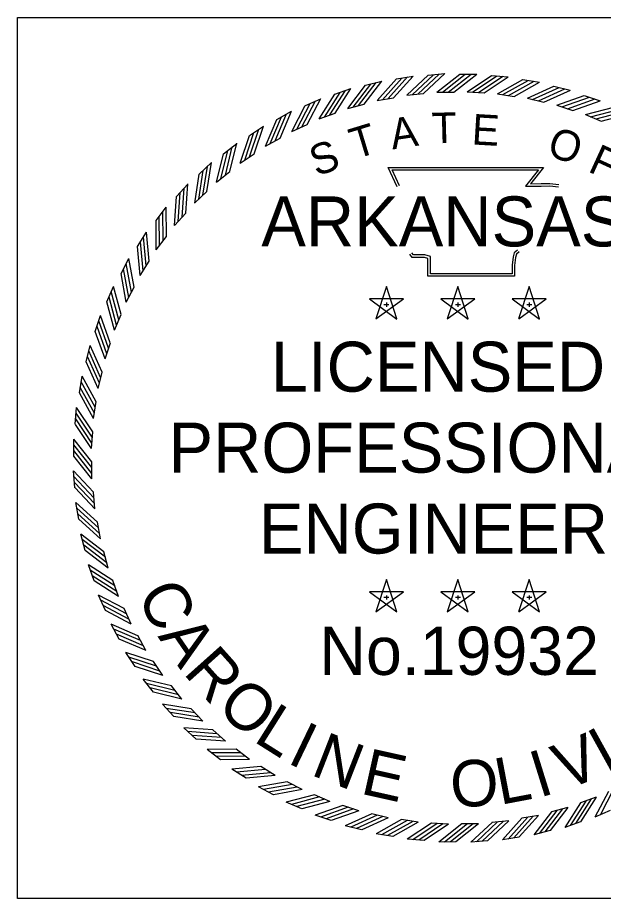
# Model space of a CAD drawing. Extents: x 0 to 1228740, y 0 to 152440.
# Drawn here: x 30.667 to 32.49, y 23.111 to 25.853 of the extents above; entities that cross this region are included whole.
import ezdxf

# ---------------------------------------------------------------- set-up
doc = ezdxf.new("R2010")
doc.units = 0
doc.layers.add('R_No Plot', color=7, linetype='Continuous')
doc.layers.add('STAMP', color=7, linetype='Continuous')

msp = doc.modelspace()

# ---------------------------------------------------------------- linework, layer by layer
at = {"layer": 'R_No Plot'}
msp.add_lwpolyline([(30.6665, 25.8526), (33.4082, 25.8526), (33.4082, 23.1109), (30.6665, 23.1109)], close=True, dxfattribs=at)
at = {"layer": 'STAMP'}
for p, q in [((31.846, 25.6616), (31.8976, 25.6707)), ((31.9441, 25.6733), (31.9963, 25.6782)), ((32.0433, 25.6763), (32.0957, 25.6763)), ((32.1415, 25.6723), (32.1937, 25.6685)), ((31.7492, 25.6419), (31.7999, 25.6552)), ((32.2394, 25.6596), (32.2912, 25.6515)), ((32.336, 25.6389), (32.3869, 25.6265)), ((31.6544, 25.6142), (31.7038, 25.6316)), ((31.878, 25.6113), (31.9303, 25.6161)), ((31.9718, 25.6205), (32.0243, 25.6205)), ((32.0661, 25.622), (32.1184, 25.6181)), ((32.1601, 25.6157), (32.212, 25.6075)), ((32.4305, 25.6102), (32.4802, 25.5936)), ((31.5622, 25.5787), (31.61, 25.6002)), ((31.6942, 25.5697), (31.745, 25.5831)), ((31.7853, 25.5943), (31.837, 25.6034)), ((32.2533, 25.6016), (32.3044, 25.5892)), ((31.4732, 25.5358), (31.5191, 25.5611)), ((31.6056, 25.5377), (31.6551, 25.5552)), ((32.3451, 25.5799), (32.3949, 25.5633)), ((32.4347, 25.5507), (32.483, 25.53)), ((31.3881, 25.4857), (31.4317, 25.5147)), ((31.5198, 25.4985), (31.5677, 25.5201)), ((31.4376, 25.4524), (31.4836, 25.4778)), ((31.3074, 25.4287), (31.3485, 25.4612)), ((31.3595, 25.3996), (31.4032, 25.4287)), ((31.2317, 25.3652), (31.2699, 25.4011)), ((31.2861, 25.3405), (31.3272, 25.3732)), ((31.1615, 25.2957), (31.1967, 25.3346)), ((31.2177, 25.2756), (31.256, 25.3115)), ((31.0973, 25.2207), (31.1291, 25.2623)), ((31.1549, 25.2053), (31.1902, 25.2442)), ((31.0395, 25.1406), (31.0677, 25.1847)), ((31.0982, 25.13), (31.1301, 25.1717)), ((30.9885, 25.056), (31.013, 25.1023)), ((31.0479, 25.0503), (31.0762, 25.0945)), ((30.9447, 24.9674), (30.9653, 25.0156)), ((31.0043, 24.9667), (31.0289, 25.0131)), ((31.8143, 25.0151), (31.7815, 24.9145)), ((31.847, 24.9146), (31.8144, 25.0152)), ((32.0366, 25.0151), (32.0038, 24.9145)), ((32.0693, 24.9146), (32.0367, 25.0152)), ((32.2589, 25.0151), (32.2261, 24.9145)), ((32.2915, 24.9146), (32.2589, 25.0152)), ((31.8672, 24.9767), (31.7614, 24.9768)), ((31.7615, 24.9767), (31.847, 24.9144)), ((31.7817, 24.9146), (31.8673, 24.9767)), ((31.8068, 24.9598), (31.8225, 24.9598)), ((31.8144, 24.9654), (31.8144, 24.9522)), ((32.0894, 24.9767), (31.9837, 24.9768)), ((31.9837, 24.9767), (32.0693, 24.9144)), ((32.0039, 24.9146), (32.0896, 24.9767)), ((32.0291, 24.9598), (32.0448, 24.9598)), ((32.0367, 24.9654), (32.0367, 24.9522)), ((32.3117, 24.9767), (32.2059, 24.9768)), ((32.206, 24.9767), (32.2915, 24.9144)), ((32.2262, 24.9146), (32.3118, 24.9767)), ((32.2513, 24.9598), (32.2671, 24.9598)), ((32.259, 24.9654), (32.259, 24.9522)), ((30.9083, 24.8756), (30.9248, 24.9253)), ((30.9678, 24.8798), (30.9885, 24.9281)), ((30.9386, 24.7901), (30.9552, 24.84)), ((30.8796, 24.7811), (30.892, 24.832)), ((30.8588, 24.6845), (30.867, 24.7363)), ((30.9169, 24.6984), (30.9293, 24.7494)), ((30.9028, 24.6052), (30.911, 24.6571)), ((30.8461, 24.5866), (30.85, 24.6388)), ((30.8415, 24.4879), (30.8411, 24.5403)), ((30.8965, 24.5111), (30.9003, 24.5635)), ((30.898, 24.4169), (30.8975, 24.4694)), ((30.8451, 24.3892), (30.8403, 24.4413)), ((30.9072, 24.3231), (30.9024, 24.3754)), ((30.8568, 24.2911), (30.8477, 24.3427)), ((30.9242, 24.2303), (30.915, 24.2821)), ((30.8766, 24.1943), (30.8633, 24.245)), ((30.9487, 24.1393), (30.9354, 24.1901)), ((30.9043, 24.0995), (30.8868, 24.1489)), ((30.9807, 24.0507), (30.9632, 24.1002)), ((31.8143, 24.1037), (31.7815, 24.0031)), ((31.847, 24.0032), (31.8144, 24.1038)), ((32.0366, 24.1037), (32.0038, 24.0031)), ((32.0693, 24.0032), (32.0367, 24.1038)), ((32.2589, 24.1037), (32.2261, 24.0031)), ((32.2915, 24.0032), (32.2589, 24.1038)), ((30.9398, 24.0073), (30.9183, 24.0551)), ((31.8672, 24.0653), (31.7614, 24.0654)), ((31.7615, 24.0653), (31.847, 24.0031)), ((31.7817, 24.0032), (31.8673, 24.0653)), ((31.8068, 24.0484), (31.8225, 24.0484)), ((31.8144, 24.0541), (31.8144, 24.0408)), ((32.0894, 24.0653), (31.9837, 24.0654)), ((31.9837, 24.0653), (32.0693, 24.0031)), ((32.0039, 24.0032), (32.0896, 24.0653)), ((32.0291, 24.0484), (32.0448, 24.0484)), ((32.0367, 24.0541), (32.0367, 24.0408)), ((32.3117, 24.0653), (32.2059, 24.0654)), ((32.206, 24.0653), (32.2915, 24.0031)), ((32.2262, 24.0032), (32.3118, 24.0653)), ((32.2513, 24.0484), (32.2671, 24.0484)), ((32.259, 24.0541), (32.259, 24.0408)), ((31.0199, 23.9649), (30.9984, 24.0128)), ((30.9827, 23.9183), (30.9573, 23.9642)), ((31.0661, 23.8827), (31.0407, 23.9287)), ((31.0328, 23.8332), (31.0038, 23.8768)), ((31.1189, 23.8046), (31.0897, 23.8483)), ((31.0898, 23.7525), (31.0572, 23.7936)), ((31.1779, 23.7311), (31.1453, 23.7723)), ((31.1533, 23.6768), (31.1174, 23.715)), ((31.2429, 23.6628), (31.2069, 23.7011)), ((31.2227, 23.6066), (31.1839, 23.6417)), ((31.3132, 23.6), (31.2742, 23.6352)), ((31.2978, 23.5424), (31.2562, 23.5742)), ((31.3885, 23.5433), (31.3467, 23.5752)), ((31.3779, 23.4846), (31.3338, 23.5128)), ((31.4682, 23.493), (31.424, 23.5213)), ((31.5518, 23.4494), (31.5054, 23.474)), ((31.4625, 23.4336), (31.4162, 23.4581)), ((31.6387, 23.4129), (31.5904, 23.4335)), ((32.4678, 23.4258), (32.4183, 23.4083)), ((31.551, 23.3897), (31.5028, 23.4103)), ((31.7283, 23.3837), (31.6785, 23.4003)), ((32.3791, 23.3938), (32.3283, 23.3805)), ((31.6429, 23.3534), (31.5931, 23.3699)), ((31.8201, 23.362), (31.769, 23.3744)), ((32.2881, 23.3693), (32.2364, 23.3601)), ((32.5112, 23.3848), (32.4634, 23.3634)), ((31.7374, 23.3247), (31.6865, 23.3371)), ((31.9133, 23.3479), (31.8614, 23.3561)), ((32.0073, 23.3416), (31.9549, 23.3454)), ((32.1016, 23.343), (32.0491, 23.3426)), ((32.1954, 23.3523), (32.1431, 23.3475)), ((32.419, 23.3494), (32.3696, 23.3319)), ((31.834, 23.3039), (31.7822, 23.3121)), ((32.3242, 23.3217), (32.2735, 23.3084)), ((31.9319, 23.2912), (31.8797, 23.2951)), ((32.0306, 23.2866), (31.9782, 23.2861)), ((32.1293, 23.2902), (32.0771, 23.2854)), ((32.2274, 23.3019), (32.1758, 23.2928))]:
    msp.add_line(p, q, dxfattribs=at)
for points in [[(31.8018, 25.597), (31.8626, 25.6643)], [(31.8197, 25.6006), (31.8804, 25.6679)], [(31.8369, 25.6034), (31.8976, 25.6708)], [(31.8779, 25.6112), (31.944, 25.6733)], [(31.8947, 25.6126), (31.9608, 25.6747)], [(31.9128, 25.6147), (31.9789, 25.6768)], [(31.9302, 25.6161), (31.9963, 25.6782)], [(31.9717, 25.6205), (32.0432, 25.6762)], [(31.9886, 25.6203), (32.0601, 25.6761)], [(32.0068, 25.6207), (32.0783, 25.6765)], [(32.0243, 25.6205), (32.0958, 25.6763)], [(32.066, 25.6219), (32.1414, 25.6723)], [(32.0828, 25.6205), (32.1582, 25.6709)], [(32.101, 25.6196), (32.1764, 25.67)], [(32.1184, 25.6182), (32.1938, 25.6685)], [(31.6942, 25.5697), (31.7491, 25.6418)], [(31.7105, 25.5738), (31.7655, 25.6459)], [(31.728, 25.5788), (31.783, 25.6509)], [(31.745, 25.5831), (31.7999, 25.6552)], [(31.7852, 25.5942), (31.8459, 25.6616)], [(32.16, 25.6156), (32.2393, 25.6596)], [(32.1767, 25.6128), (32.256, 25.6568)], [(32.1947, 25.6104), (32.274, 25.6544)], [(32.2119, 25.6075), (32.2912, 25.6515)], [(32.2532, 25.6016), (32.3359, 25.6388)], [(31.6055, 25.5377), (31.6543, 25.6141)], [(31.6215, 25.5431), (31.6703, 25.6196)], [(31.6385, 25.5496), (31.6873, 25.626)], [(31.655, 25.5553), (31.7038, 25.6317)], [(32.2696, 25.5974), (32.3523, 25.6347)], [(32.2874, 25.5935), (32.37, 25.6308)], [(32.3043, 25.5892), (32.387, 25.6265)], [(32.345, 25.5799), (32.4304, 25.6102)], [(31.5352, 25.5052), (31.5776, 25.5854)], [(31.5517, 25.5131), (31.594, 25.5932)], [(31.5677, 25.5201), (31.61, 25.6003)], [(32.3609, 25.5744), (32.4464, 25.6047)], [(32.3783, 25.569), (32.4638, 25.5993)], [(32.3948, 25.5633), (32.4803, 25.5937)], [(31.4682, 25.4695), (31.5038, 25.5529)], [(31.4835, 25.4778), (31.5191, 25.5612)], [(31.5198, 25.4985), (31.5621, 25.5786)], [(32.4346, 25.5506), (32.5223, 25.5738)], [(32.4501, 25.5439), (32.5377, 25.567)], [(32.4669, 25.5371), (32.5546, 25.5602)], [(32.4829, 25.5301), (32.5706, 25.5532)], [(31.4376, 25.4523), (31.4732, 25.5357)], [(31.4524, 25.4603), (31.488, 25.5437)], [(31.3886, 25.4192), (31.4171, 25.5052)], [(31.4032, 25.4287), (31.4317, 25.5148)], [(31.3595, 25.3995), (31.3881, 25.4856)], [(31.3736, 25.4087), (31.4022, 25.4948)], [(31.3134, 25.3624), (31.3347, 25.4506)], [(31.3271, 25.3732), (31.3485, 25.4613)], [(31.286, 25.3405), (31.3074, 25.4286)], [(31.2993, 25.3508), (31.3207, 25.4389)], [(31.2431, 25.2997), (31.2571, 25.3893)], [(31.2559, 25.3115), (31.27, 25.4011)], [(31.2177, 25.2755), (31.2317, 25.3651)], [(31.2301, 25.287), (31.2441, 25.3765)], [(31.8481, 25.3255), (31.8201, 25.386), (32.3034, 25.3863), (32.2631, 25.3356), (32.2959, 25.336), (32.3233, 25.3364), (32.3507, 25.3334)], [(31.855, 25.3288), (31.8321, 25.3784), (32.2876, 25.3787), (32.247, 25.3277), (32.296, 25.3284), (32.3229, 25.3287), (32.3499, 25.3258)], [(31.1901, 25.2442), (31.1967, 25.3347)], [(31.1664, 25.2176), (31.1729, 25.308)], [(31.1783, 25.2314), (31.1848, 25.3218)], [(31.1549, 25.2052), (31.1615, 25.2956)], [(31.13, 25.1717), (31.1291, 25.2624)], [(31.1086, 25.1432), (31.1076, 25.2339)], [(31.1193, 25.1579), (31.1184, 25.2486)], [(31.0982, 25.1299), (31.0973, 25.2206)], [(31.0666, 25.0799), (31.0582, 25.1701)], [(31.0761, 25.0945), (31.0677, 25.1848)], [(31.0571, 25.0643), (31.0487, 25.1546)], [(31.0479, 25.0502), (31.0395, 25.1405)], [(32.2273, 25.123), (32.219, 25.1163), (32.2163, 25.1063), (32.2136, 25.0812), (32.2136, 25.0478), (31.9438, 25.0478), (31.9438, 25.0929), (31.9438, 25.1029), (31.9328, 25.1063), (31.8944, 25.1063), (31.8876, 25.1167)], [(32.2224, 25.129), (32.2123, 25.1207), (32.2088, 25.1077), (32.2059, 25.0816), (32.2059, 25.0555), (31.9514, 25.0555), (31.9514, 25.0929), (31.9514, 25.1086), (31.934, 25.1139), (31.8986, 25.1139), (31.894, 25.1209)], [(31.0205, 24.9977), (31.0047, 25.087)], [(31.0288, 25.0131), (31.013, 25.1023)], [(31.0124, 24.9814), (30.9965, 25.0707)], [(31.0043, 24.9666), (30.9885, 25.0559)], [(30.9884, 24.928), (30.9652, 25.0157)], [(30.9746, 24.8951), (30.9514, 24.9828)], [(30.9814, 24.912), (30.9582, 24.9997)], [(30.9678, 24.8797), (30.9447, 24.9674)], [(30.9551, 24.8399), (30.9248, 24.9254)], [(30.9495, 24.8234), (30.9191, 24.9089)], [(30.9386, 24.7901), (30.9083, 24.8755)], [(30.9441, 24.806), (30.9138, 24.8915)], [(30.925, 24.7325), (30.8877, 24.8151)], [(30.9292, 24.7494), (30.892, 24.8321)], [(30.921, 24.7147), (30.8838, 24.7973)], [(30.9169, 24.6983), (30.8796, 24.781)], [(30.9109, 24.657), (30.867, 24.7363)], [(30.9081, 24.6398), (30.8641, 24.7191)], [(30.9028, 24.6051), (30.8589, 24.6844)], [(30.9056, 24.6218), (30.8617, 24.7011)], [(30.8989, 24.5461), (30.8485, 24.6215)], [(30.9003, 24.5635), (30.8499, 24.6389)], [(30.8979, 24.5279), (30.8476, 24.6033)], [(30.8965, 24.5111), (30.8462, 24.5865)], [(30.8974, 24.4693), (30.841, 24.5403)], [(30.8974, 24.4519), (30.841, 24.5229)], [(30.898, 24.4337), (30.8416, 24.5047)], [(30.898, 24.4168), (30.8416, 24.4878)], [(30.9024, 24.3753), (30.8403, 24.4414)], [(30.9038, 24.3579), (30.8417, 24.424)], [(30.9059, 24.3398), (30.8438, 24.4059)], [(30.9073, 24.323), (30.8452, 24.3891)], [(30.915, 24.282), (30.8477, 24.3427)], [(30.9179, 24.2648), (30.8506, 24.3255)], [(30.9215, 24.2469), (30.8541, 24.3076)], [(30.9242, 24.2303), (30.8569, 24.291)], [(30.9354, 24.1901), (30.8632, 24.245)], [(30.9396, 24.1731), (30.8675, 24.2281)], [(30.9447, 24.1556), (30.8725, 24.2106)], [(30.9488, 24.1393), (30.8767, 24.1942)], [(30.9632, 24.1001), (30.8868, 24.1489)], [(30.9689, 24.0836), (30.8925, 24.1324)], [(30.9753, 24.0666), (30.8989, 24.1154)], [(30.9808, 24.0506), (30.9044, 24.0994)], [(30.9984, 24.0128), (30.9182, 24.0551)], [(31.0054, 23.9968), (30.9252, 24.0391)], [(31.0132, 23.9803), (30.9331, 24.0227)], [(31.02, 23.9649), (30.9398, 24.0072)], [(31.0407, 23.9286), (30.9573, 23.9642)], [(31.049, 23.9133), (30.9656, 23.9488)], [(31.0581, 23.8975), (30.9747, 23.9331)], [(31.0662, 23.8827), (30.9828, 23.9183)], [(31.0897, 23.8483), (31.0037, 23.8768)], [(31.0993, 23.8336), (31.0132, 23.8622)], [(31.1097, 23.8187), (31.0237, 23.8473)], [(31.119, 23.8046), (31.0329, 23.8332)], [(31.1453, 23.7722), (31.0572, 23.7936)], [(31.156, 23.7584), (31.0679, 23.7798)], [(31.1676, 23.7444), (31.0795, 23.7658)], [(31.178, 23.7311), (31.0899, 23.7525)], [(31.2069, 23.701), (31.1174, 23.715)], [(31.2188, 23.6882), (31.1292, 23.7022)], [(31.2315, 23.6752), (31.1419, 23.6892)], [(31.2429, 23.6628), (31.1533, 23.6768)], [(31.2742, 23.6352), (31.1838, 23.6417)], [(31.2871, 23.6234), (31.1967, 23.6299)], [(31.3009, 23.6115), (31.2104, 23.618)], [(31.3133, 23.6), (31.2228, 23.6066)], [(31.3468, 23.5751), (31.2561, 23.5742)], [(31.3605, 23.5644), (31.2699, 23.5635)], [(31.3752, 23.5537), (31.2846, 23.5527)], [(31.3886, 23.5433), (31.2979, 23.5424)], [(31.424, 23.5212), (31.3337, 23.5128)], [(31.4386, 23.5117), (31.3483, 23.5033)], [(31.4542, 23.5022), (31.3639, 23.4938)], [(31.4683, 23.493), (31.378, 23.4846)], [(31.5054, 23.4739), (31.4161, 23.4581)], [(31.5208, 23.4656), (31.4315, 23.4498)], [(31.537, 23.4574), (31.4478, 23.4416)], [(31.5519, 23.4494), (31.4626, 23.4336)], [(32.5057, 23.4435), (32.4634, 23.3633)], [(32.5217, 23.4505), (32.4794, 23.3703)], [(31.5904, 23.4335), (31.5028, 23.4103)], [(31.6064, 23.4265), (31.5188, 23.4033)], [(31.6233, 23.4197), (31.5357, 23.3965)], [(32.4519, 23.4204), (32.4031, 23.344)], [(32.4679, 23.4259), (32.419, 23.3495)], [(31.6388, 23.4129), (31.5511, 23.3898)], [(31.6785, 23.4002), (31.5931, 23.3699)], [(31.695, 23.3945), (31.6096, 23.3642)], [(31.7124, 23.3892), (31.627, 23.3589)], [(32.3628, 23.3897), (32.3079, 23.3176)], [(32.3792, 23.3939), (32.3242, 23.3218)], [(32.4184, 23.4083), (32.3695, 23.3319)], [(32.4349, 23.414), (32.3861, 23.3376)], [(31.7284, 23.3837), (31.6429, 23.3534)], [(31.7691, 23.3743), (31.6864, 23.3371)], [(31.786, 23.37), (31.7033, 23.3328)], [(31.8038, 23.3661), (31.7211, 23.3289)], [(31.8201, 23.362), (31.7375, 23.3247)], [(32.2365, 23.3601), (32.1757, 23.2928)], [(32.2537, 23.363), (32.193, 23.2957)], [(32.2715, 23.3665), (32.2108, 23.2992)], [(32.2882, 23.3693), (32.2275, 23.302)], [(32.3284, 23.3804), (32.2735, 23.3083)], [(32.3453, 23.3847), (32.2904, 23.3126)], [(31.8614, 23.356), (31.7821, 23.3121)], [(31.8787, 23.3531), (31.7994, 23.3092)], [(31.8967, 23.3507), (31.8174, 23.3067)], [(31.9133, 23.3479), (31.834, 23.304)], [(31.955, 23.3454), (31.8796, 23.295)], [(31.9724, 23.3439), (31.897, 23.2936)], [(31.9906, 23.343), (31.9152, 23.2926)], [(32.0074, 23.3416), (31.932, 23.2913)], [(32.0491, 23.3425), (31.9781, 23.2861)], [(32.0666, 23.3425), (31.9956, 23.2861)], [(32.0848, 23.3431), (32.0138, 23.2867)], [(32.1016, 23.3431), (32.0307, 23.2867)], [(32.1432, 23.3474), (32.0771, 23.2854)], [(32.1606, 23.3489), (32.0945, 23.2868)], [(32.1786, 23.351), (32.1126, 23.2889)], [(32.1955, 23.3523), (32.1294, 23.2903)]]:
    msp.add_lwpolyline(points, dxfattribs=at)

# ---------------------------------------------------------------- texts
for s, height, rotation, p in [('T', 0.0953, 1.4789, (31.9564, 25.4609)), ('A', 0.0953, 8.6788, (31.8333, 25.4419)), ('E', 0.0953, 356.672, (32.0785, 25.458)), ('T', 0.0953, 16.9015, (31.7176, 25.4117)), ('O', 0.0953, 341.2218, (32.3099, 25.4253)), ('S', 0.0953, 19.7726, (31.5964, 25.3573)), ('F', 0.0953, 335.3628, (32.4384, 25.375)), ('C', 0.1448, 296.8377, (31.036, 24.0559)), ('A', 0.1448, 304.4827, (31.1014, 23.9265)), ('R', 0.1448, 311.7637, (31.1793, 23.8124)), ('O', 0.1448, 319.7727, (31.2808, 23.6994)), ('L', 0.1448, 327.7818, (31.3971, 23.6017)), ('I', 0.1448, 334.3346, (31.5017, 23.5344)), ('I', 0.1448, 28.9418, (32.4987, 23.4965)), ('N', 0.1448, 338.7032, (31.5753, 23.4964)), ('V', 0.1448, 21.6609, (32.3702, 23.4459)), ('E', 0.1448, 347.4403, (31.7303, 23.4377)), ('I', 0.1448, 17.2923, (32.2903, 23.4235)), ('O', 0.1448, 2.7304, (32.0163, 23.3938)), ('L', 0.1448, 10.7394, (32.168, 23.4015))]:
    msp.add_text(s, height=height, rotation=rotation, dxfattribs=at).set_placement(p)
for s, height, p in [('ARKANSAS', 0.15559, (31.4251, 25.1404)), ('LICENSED', 0.15559, (31.4547, 24.6882)), ('PROFESSIONAL', 0.155594, (31.1361, 24.4362)), ('ENGINEER', 0.15559, (31.4177, 24.1843)), ('No.19932', 0.15004, (31.606, 23.8066))]:
    msp.add_text(s, height=height, dxfattribs=at).set_placement(p)

doc.saveas('drawing.dxf')
